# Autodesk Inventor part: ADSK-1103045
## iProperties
Shininess: 50.0
Length Units: 11272
Angle Units: 11279
Time Units: 11290
Mass Units: 11286
Length Display Precision: 4
Angle Display Precision: 2
Compacted: True
Created: 2000-11
Part Number: ADSK-1103045
Document SubType Name: Modeling
Description: PISTON
Mass: 6.47702 g
Surface Area: 10.9462 cm^2
Volume: 0.82615 cm^3
Density: 7.84 g/cm^3
Material: Steel, High Strength Low Alloy
Density: 0.0
Volumn: 0.0
Area: 0.0
PropertySet Name: Model Information
Control State: 0
Master: False
Checked Out: False
Author: Autodesk, Inc.
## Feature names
1. Extrusion4
2. Extrusion5
3. Fillet2
